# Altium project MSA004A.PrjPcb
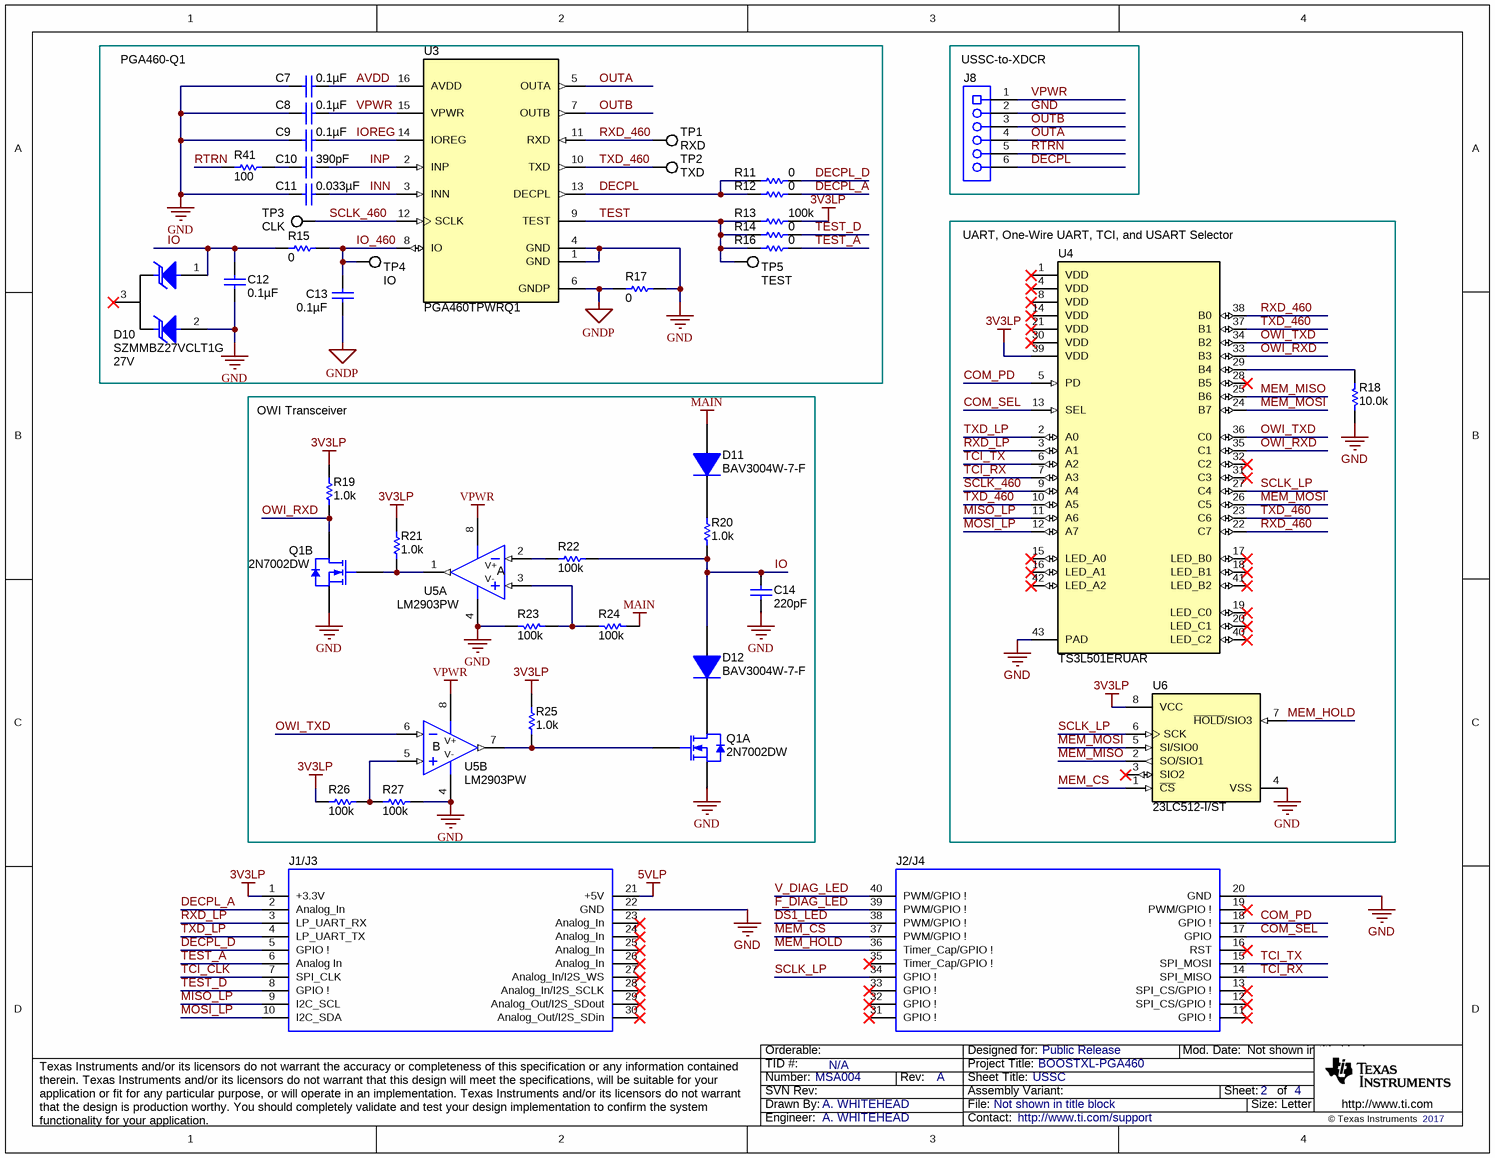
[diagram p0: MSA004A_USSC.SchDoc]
TID: N/A; TechSupport: http://www.ti.com/support; SCH_Rev: A; PRJ_Title: BOOSTXL-PGA460; PRJ_Number: MSA004; PRJ_Engineer: A. WHITEHEAD; PRJ_Customer: Public Release; PCB_Rev: A; PCB_Layout: A. WHITEHEAD; CopyrightYear: 2017
4 sheets, 119 parts. Net scope: global (net labels, ports and power ports of the same name join across sheets).
Board file: MSA004A_PCB.PcbDoc
Sheets:
  MSA004A_USSC.SchDoc
  MSA004A_HW.SchDoc
  MSA004A_XDCR.SchDoc
  MSA004A_PWR.SchDoc

## Sheet MSA004A_USSC.SchDoc: USSC
size Letter; Date: Not shown in title block; ApprovedBy: Not shown in title block; CheckedBy: Not shown in title block; Author: Not shown in title block; CompanyName: Not shown in title block; DrawnBy: A. WHITEHEAD; Engineer: Not shown in title block; Organization: Not shown in title block; Address1: Not shown in title block; Address2: Not shown in title block; Address3: Not shown in title block; Address4: Not shown in title block; DocumentNumber: 1; Revision: Use project parameter SCH_Rev; SheetNumber: 2; SheetTotal: 4; PageSetup: Record=PageOptions¦CenterHorizontal=True¦CenterVertical=True¦PrintScale=1.00¦XCorrection=1.00¦YCorrection=1.00¦PrintKind=0¦BorderSize=5000000¦LeftOffset=0¦BottomOffset=0¦Orientation=2¦PaperLength=1000¦PaperWidth=1000¦Scale=100¦PaperSource=15¦PrintQuality=600¦MediaType=1¦DitherType=10¦PaperKind=Letter¦PrintScaleMode=1

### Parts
C7  ValueDisplayed: 0.1µF  [0603]  (hidden comment: C1608X7R1H104K080AA)
C8  ValueDisplayed: 0.1µF  [0603]  (hidden comment: C1608X7R1H104K080AA)
C9  ValueDisplayed: 0.1µF  [0603]  (hidden comment: C1608X7R1H104K080AA)
C10  ValueDisplayed: 390pF  [0603]  (hidden comment: GRM1885C2A391JA01D)
C11  ValueDisplayed: 0.033µF  [0603]  (hidden comment: GRM188R71H333KA61D)
C12  ValueDisplayed: 0.1µF  [0603]  (hidden comment: C1608X7R1H104K080AA)
C13  ValueDisplayed: 0.1µF  [0603]  (hidden comment: C1608X7R1H104K080AA)
C14  ValueDisplayed: 220pF  [0603]  (hidden comment: C0603C221K5RACTU)
D10  SZMMBZ27VCLT1G  value 27V  [SOT-23]
D11  BAV3004W-7-F  [SOD-123]
D12  BAV3004W-7-F  [SOD-123]
J1/J3  SSQ-110-03-T-D  [BoosterPack_40pin_J1J3]  (value not drawn)
J2/J4  SSQ-110-03-T-D  [BoosterPack_40pin_J2J4]  (value not drawn)
J8  PPPC061LGBN-RC  [Sullins_xPxC061LGBN]  (value not drawn)
Q1  2N7002DW  [SOT-363]  (parts A,B of 2)
R11  ValueDisplayed: 0  [0402]  (hidden comment: CRCW04020000Z0ED)
R12  ValueDisplayed: 0  [0402]  (hidden comment: CRCW04020000Z0ED)
R13  ValueDisplayed: 100k  [0402]  (hidden comment: CRCW0402100KJNED)
R14  ValueDisplayed: 0  [0402]  (hidden comment: CRCW04020000Z0ED)
R15  ValueDisplayed: 0  [1206]  (hidden comment: CRCW12060000Z0EA)
R16  ValueDisplayed: 0  [0402]  (hidden comment: CRCW04020000Z0ED)
R17  ValueDisplayed: 0  [1206]  (hidden comment: CRCW12060000Z0EA)
R18  ValueDisplayed: 10.0k  [0402]  (hidden comment: CRCW040210K0FKED)
R19  ValueDisplayed: 1.0k  [0603]  (hidden comment: CRCW06031K00JNEA)
R20  ValueDisplayed: 1.0k  [2010]  (hidden comment: CRCW20101K00JNEF)
R21  ValueDisplayed: 1.0k  [0603]  (hidden comment: CRCW06031K00JNEA)
R22  ValueDisplayed: 100k  [0603]  (hidden comment: CRCW0603100KJNEA)
R23  ValueDisplayed: 100k  [0603]  (hidden comment: CRCW0603100KJNEA)
R24  ValueDisplayed: 100k  [0603]  (hidden comment: CRCW0603100KJNEA)
R25  ValueDisplayed: 1.0k  [0603]  (hidden comment: CRCW06031K00JNEA)
R26  ValueDisplayed: 100k  [0603]  (hidden comment: CRCW0603100KJNEA)
R27  ValueDisplayed: 100k  [0603]  (hidden comment: CRCW0603100KJNEA)
R41  ValueDisplayed: 100  [0603]  (hidden comment: CRCW0603100RFKEA)
TP1  RXD  [Testpoint_Keystone_Miniature]
TP2  TXD  [Testpoint_Keystone_Miniature]
TP3  CLK  [Testpoint_Keystone_Miniature]
TP4  IO  [Testpoint_Keystone_Miniature]
TP5  TEST  [Testpoint_Keystone_Miniature]
U3  PGA460TPWRQ1  [PW0016A_N]
U4  TS3L501ERUAR  [RUA0042A]
U5  LM2903PW  [PW0008A_N]  (parts A,B of 2)
U6  23LC512-I/ST  [TSSOP-8]

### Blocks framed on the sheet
PGA460-Q1: C7-C13 D10 R11-R17 R41 TP1-TP5 U3
USSC-to-XDCR: J8
UART, One-Wire UART, TCI, and USART Selector: R18 U4 U6
OWI Transceiver: C14 D11 D12 Q1 R19-R27 U5

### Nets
3V3LP: J1/J3.1(+3.3V) R13.2 R19.1 R21.2 R25.2 R26.1 U4.39(VDD) U6.8(VCC)
5VLP: J1/J3.21(+5V)
GND: C7.2 C8.2 C9.2 C11.2 C12.2 C14.2 D10.2 J1/J3.22(GND) J2/J4.20(GND) J8.2 Q1.1(S) Q1.4(S) R17.1 R18.2 R23.1 R27.1 U3.1(GND) U3.4(GND) U4.43(PAD) U5.4(V-) U6.4(VSS)
GNDP: C13.2 R17.2 U3.6(GNDP)
MAIN: D11.2(A) R24.2
VPWR: C8.1 J8.1 U3.15(VPWR) U5.8(V+)
AVDD: C7.1 U3.16(AVDD)
COM_PD: J2/J4.18(GPIO_!) U4.5(PD)
COM_SEL: J2/J4.17(GPIO) U4.13(SEL)
DECPL: J8.6 R11.1 R12.1 U3.13(DECPL)
DECPL_A: J1/J3.2(Analog_In) R12.2
DECPL_D: J1/J3.5(GPIO_!) R11.2
DS1_LED: J2/J4.38(PWM/GPIO_!)
F_DIAG_LED: J2/J4.39(PWM/GPIO_!)
INN: C11.1 U3.3(INN)
INP: C10.1 U3.2(INP)
IO: C12.1 C14.1 D10.1 D12.2(A) R15.1 R20.1 R22.2
IO_460: C13.1 R15.2 TP4.1 U3.8(IO)
IOREG: C9.1 U3.14(IOREG)
MEM_CS: J2/J4.37(PWM/GPIO_!) U6.1(~{CS})
MEM_HOLD: J2/J4.36(Timer_Cap/GPIO_!) U6.7(~{HOLD}/SIO3)
MEM_MISO: U4.25(B6) U6.2(SO/SIO1)
MEM_MOSI: U4.24(B7) U4.26(C5) U6.5(SI/SIO0)
MISO_LP: J1/J3.9(I2C_SCL) U4.11(A6)
MOSI_LP: J1/J3.10(I2C_SDA) U4.12(A7)
OUTA: J8.4 U3.5(OUTA)
OUTB: J8.3 U3.7(OUTB)
OWI_RXD: Q1.3(D) R19.2 U4.33(B3) U4.35(C1)
OWI_TXD: U4.34(B2) U4.36(C0) U5.6(IN-)
RTRN: J8.5 R41.1
RXD_460: TP1.1 U3.11(RXD) U4.22(C7) U4.38(B0)
RXD_LP: J1/J3.3(LP_UART_RX) U4.3(A1)
SCLK_460: TP3.1 U3.12(SCLK) U4.9(A4)
SCLK_LP: J2/J4.34(GPIO_!) U4.27(C4) U6.6(SCK)
TCI_CLK: J1/J3.7(SPI_CLK)
TCI_RX: J2/J4.14(SPI_MISO) U4.7(A3)
TCI_TX: J2/J4.15(SPI_MOSI) U4.6(A2)
TEST: R13.1 R14.1 R16.1 TP5.1 U3.9(TEST)
TEST_A: J1/J3.6(Analog_In) R16.2
TEST_D: J1/J3.8(GPIO_!) R14.2
TXD_460: TP2.1 U3.10(TXD) U4.10(A5) U4.23(C6) U4.37(B1)
TXD_LP: J1/J3.4(LP_UART_TX) U4.2(A0)
V_DIAG_LED: J2/J4.40(PWM/GPIO_!)
NetC10_2: C10.2 R41.2
NetD11_1: D11.1(K) R20.2
NetD12_1: D12.1(K) Q1.6(D)
NetQ1_2: Q1.2(G) R25.1 U5.7(OUT)
NetQ1_5: Q1.5(G) R21.1 U5.1(OUT)
NetR18_1: R18.1 U4.29(B4)
NetR22_1: R22.1 U5.2(IN-)
NetR23_2: R23.2 R24.1 U5.3(IN+)
NetR26_2: R26.2 R27.2 U5.5(IN+)

Not connected (* = marked no-connect by the designer): D10 3*; J1/J3 23(Analog_In)* 24(Analog_In)* 25(Analog_In)* 26(Analog_In)* 27(Analog_In/I2S_WS)* 28(Analog_In/I2S_SCLK)* 29(Analog_Out/I2S_SDout)* 30(Analog_Out/I2S_SDin)*; J2/J4 11(GPIO_!)* 12(SPI_CS/GPIO_!)* 13(SPI_CS/GPIO_!)* 16(RST)* 19(PWM/GPIO_!)* 31(GPIO_!)* 32(GPIO_!)* 33(GPIO_!)* 35(Timer_Cap/GPIO_!)*; U4 1(VDD)* 4(VDD)* 8(VDD)* 14(VDD)* 15(LED_A0)* 16(LED_A1)* 17(LED_B0)* 18(LED_B1)* 19(LED_C0)* 20(LED_C1)* 21(VDD)* 28(B5)* 30(VDD)* 31(C3)* 32(C2)* 40(LED_C2)* 41(LED_B2)* 42(LED_A2)*; U6 3(SIO2)*

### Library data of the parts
C7-C9 C12 C13 = C1608X7R1H104K080AA: CAP, CERM, 0.1 µF, 50 V, +/- 10%, X7R, 0603; Manufacturer: TDK; Polarized: N; CompType: Capacitor; Value: 0.1uF; U/M: EA; Cap_F: 0.0000001; Tolerance_%: 10; Value1: Unknown; VDC_V: 50; Value2: 50V; TaMin_C: -55; TaMax_C: 125; AEC Category: Q200
C10 = GRM1885C2A391JA01D: CAP, CERM, 390 pF, 100 V, +/- 5%, C0G/NP0, 0603; Manufacturer: MuRata; Polarized: N; CompType: Capacitor; Value: 390pF; U/M: EA; Cap_F: 0.00000000039; Tolerance_%: 5; Value1: Unknown; VDC_V: 100; Value2: 100V; TaMin_C: -55; TaMax_C: 125; AEC Category: Q200; SizeArea_mm2: 1.28; SizeAreaWB_mm2: 4.68; SizeX_mm: 1.6; SizeY_mm: 0.8; SizeZ_mm: 1
C11 = GRM188R71H333KA61D: CAP, CERM, 0.033 µF, 50 V, +/- 10%, X7R, 0603; Manufacturer: MuRata; Polarized: N; CompType: Capacitor; Value: 0.033uF; U/M: EA; Cap_F: 0.000000033; Tolerance_%: 10; Value1: Unknown; VDC_V: 50; Value2: 50V; TaMin_C: -55; TaMax_C: 125; AEC Category: Q200; SizeArea_mm2: 1.28; SizeAreaWB_mm2: 4.68; SizeX_mm: 1.6; SizeY_mm: 0.8; SizeZ_mm: 1
C14 = C0603C221K5RACTU: CAP, CERM, 220 pF, 50 V, +/- 10%, X7R, 0603; Manufacturer: Kemet; Polarized: N; CompType: Capacitor; Value: 220pF; U/M: EA; Cap_F: 0.00000000022; Tolerance_%: 10; Value1: Unknown; VDC_V: 50; Value2: 50V; TaMin_C: -55; TaMax_C: 125; AEC Category: Q200
D10 = SZMMBZ27VCLT1G: Diode, TVS, Uni, 27 V, 40 W, SOT-23; Manufacturer: ON Semiconductor; SymbolCreator: a0411947; U/M: EA; Power_W: 40; Vr_V: 27; Value1: 40W; RJA_CperW: 556; SizeAreaWB_mm2: 14; SizeArea_mm2: 7.5; SizeX_mm: 2.5; SizeY_mm: 3; SizeZ_mm: 1.1; AEC Category: Q101
D11 D12 = BAV3004W-7-F: Diode, Switching, 350 V, 0.225 A, SOD-123; Manufacturer: Diodes Inc.; U/M: EA; Vf_V: 1.25; Value: 350V; Value1: 0.225A; Value2: 1.25V; Io_A: 0.225; Vr_V: 350; TJmax_C: 150; AEC Category: Q101
J1/J3 = BoosterPack_40pin_J1J3: Receptacle, 2.54mm, 10x2, Tin, TH; Manufacturer: Samtec; Alternate Manufacturer: Major League Electronics; Alternate PartNumber: CRD-081413-A-G; SymbolCreator: a0412235; Note: Booster Pack 40 pin J1 and J3
J2/J4 = BoosterPack_40pin_J2J4: Receptacle, 2.54mm, 10x2, Tin, TH; Manufacturer: Samtec; Alternate Manufacturer: Major League Electronics; Alternate PartNumber: CRD-081413-A-G; SymbolCreator: a0412235; Note: Booster Pack 40 pin J2 and J4
J8 = PPPC061LGBN-RC: Receptacle, 2.54mm, 6x1, Gold, R/A, Black, TH; Manufacturer: Sullins Connector Solutions; SymbolCreator: a0411947; Pitch_mm: 2.54; Gender: Female; Row_Count: 1; Current_A: 3; Voltage_V: 250; Cert_UL: Y
Q1 = 2N7002DW: MOSFET, N-CH, 60 V, 0.115 A, SOT-363; Manufacturer: Fairchild Semiconductor; Alternate Manufacturer: None; U/M: EA; ChType: N; Value: 60V; VdsMax_V: 60; Value1: ? ohm; Value2: ? nC; Vgs_V: 20; IdsMax_A: 0.115; SizeAreaWB_mm2: 10.24; SizeArea_mm2: 4.84; SizeX_mm: 2.2; SizeZ_mm: 1.1; AEC Category: Q101
R11 R12 R14 R16 = CRCW04020000Z0ED: RES, 0, 5%, 0.063 W, 0402; Manufacturer: Vishay-Dale; CompType: Resistor; Value: 0; Value_Code: 0000; Tolerance_%: 5; Power_W: 0.063; Value2: 0.063W; VDC_V: 50; TempCo: 200 ppm/C; SizeArea_mm2: 0.5; SizeX_mm: 1; SizeZ_mm: 0.6; EIA_Code: E24; U/M: EA; AEC Category: Q200
R13 = CRCW0402100KJNED: RES, 100 k, 5%, 0.063 W, 0402; Manufacturer: Vishay-Dale; CompType: Resistor; Value: 100k; Res_ohm: 100000; Tolerance_%: 5; Power_W: 0.063; Value2: 0.063W; VDC_V: 50; TempCo: 200 ppm/C; SizeArea_mm2: 0.5; SizeX_mm: 1; SizeZ_mm: 0.6; EIA_Code: E24; U/M: EA; AEC Category: Q200
R15 = CRCW12060000Z0EA: RES, 0, 5%, 0.25 W, 1206; Manufacturer: Vishay-Dale; CompType: Resistor; Value: 0; Value_Code: 0000; Tolerance_%: 5; Power_W: 0.25; Value2: 0.25W; VDC_V: 200; TempCo: 200 ppm/C; EIA_Code: E24; U/M: EA; AEC Category: Q200; SizeArea_mm2: 5.12; SizeX_mm: 3.2; SizeY_mm: 1.6; SizeZ_mm: 1.35
R17 = CRCW12060000Z0EA: RES, 0, 5%, 0.25 W, 1206; Manufacturer: Vishay-Dale; CompType: Resistor; Value: 0; Value2: 0.25W; Value_Code: 0000; Tolerance_%: 5; Power_W: 0.25; VDC_V: 200; TempCo: 200 ppm/C; EIA_Code: E24; U/M: EA; AEC Category: Q200; SizeArea_mm2: 5.12; SizeX_mm: 3.2; SizeY_mm: 1.6; SizeZ_mm: 1.35
R18 = CRCW040210K0FKED: RES, 10.0 k, 1%, 0.063 W, 0402; Manufacturer: Vishay-Dale; CompType: Resistor; Value: 10.0k; Res_ohm: 10000; Value_Code: 10k0; Tolerance_%: 1; Power_W: 0.063; Value2: 0.063W; VDC_V: 50; TempCo: 100 ppm/C; SizeArea_mm2: 0.5; SizeZ_mm: 0.6; EIA_Code: E96; U/M: EA; AEC Category: Q200
R19 R21 R25 = CRCW06031K00JNEA: RES, 1.0 k, 5%, 0.1 W, 0603; Manufacturer: Vishay-Dale; CompType: Resistor; Value: 1.0k; Res_ohm: 1000; Value_Code: 1k00; Tolerance_%: 5; Power_W: 0.1; Value2: 0.1W; VDC_V: 75; TempCo: 200 ppm/C; SizeArea_mm2: 1.28; SizeX_mm: 1.6; SizeY_mm: 0.8; SizeZ_mm: 1; EIA_Code: E24; U/M: EA; AEC Category: Q200
R20 = CRCW20101K00JNEF: RES, 1.0 k, 5%, 0.75 W, AEC-Q200 Grade 0, 2010; Manufacturer: Vishay-Dale; CompType: Resistor; Value: 1.0k; Res_ohm: 1000; Value_Code: 1k00; Tolerance_%: 5; Power_W: 0.75; Value2: 0.75W; VDC_V: 400; TempCo: 200 ppm/C; SizeArea_mm2: 12.5; SizeY_mm: 2.5; SizeZ_mm: 1.66; EIA_Code: E24; U/M: EA; AEC Category: Q200; AEC Qualified: Y; AEC Grade: 0
R22-R24 R26 R27 = CRCW0603100KJNEA: RES, 100 k, 5%, 0.1 W, 0603; Manufacturer: Vishay-Dale; CompType: Resistor; Value: 100k; Res_ohm: 100000; Tolerance_%: 5; Power_W: 0.1; Value2: 0.1W; VDC_V: 75; TempCo: 200 ppm/C; EIA_Code: E24; U/M: EA; AEC Category: Q200
R41 = CRCW0603100RFKEA: RES, 100, 1%, 0.1 W, 0603; Manufacturer: Vishay-Dale; CompType: Resistor; Value: 100; Value_Code: 100R; Tolerance_%: 1; Power_W: 0.1; Value2: 0.1W; VDC_V: 75; TempCo: 100 ppm/C; SizeArea_mm2: 1.28; SizeX_mm: 1.6; SizeY_mm: 0.8; EIA_Code: E96; U/M: EA; AEC Category: Q200
TP1-TP5 = 5015: Test Point, Miniature, SMT; Manufacturer: Keystone; CompType: Test Point Loop
U3 = PGA460TPWRQ1: PGA460TPWRQ1, PW0016A; Manufacturer: Texas Instruments; SymbolCreator: Altium; SizeArea_mm2: 32; SizeAreaWB_mm2: 58.8; SizeX_mm: 6.4; SizeY_mm: 5; SizeZ_mm: 1.2; CompType: IC; U/M: EA
U4 = TS3L501ERUAR: 16-BIT TO 8-BIT MULTIPLEXER/DEMULTIPLEXER GIGABIT ETHERNET LAN SWITCH WITH POWER DOWN MODE, RUA0042A; Manufacturer: Texas Instruments; SymbolCreator: a0411947; SizeArea_mm2: 31.5; SizeAreaWB_mm2: 60.5; SizeX_mm: 3.5; SizeY_mm: 9; SizeZ_mm: 0.8; CompType: IC; U/M: EA
U5 = LM2903PW: Dual Comparator, PW0008A; Manufacturer: Texas Instruments; CompType: OpAmp IC
U6 = 23LC512-I/ST: 512Kbit SPI Serial SRAM with SDI and SQI Interface,; Manufacturer: Microchip; SymbolCreator: a0411947

## Sheet MSA004A_HW.SchDoc: Hardware
size Letter; Date: Not shown in title block; ApprovedBy: Not shown in title block; CheckedBy: Not shown in title block; Author: Not shown in title block; CompanyName: Not shown in title block; DrawnBy: A. WHITEHEAD; Engineer: Not shown in title block; Organization: Not shown in title block; Address1: Not shown in title block; Address2: Not shown in title block; Address3: Not shown in title block; Address4: Not shown in title block; DocumentNumber: 2; Revision: Use project parameter SCH_Rev; SheetNumber: 4; SheetTotal: 4; PageSetup: Record=PageOptions¦CenterHorizontal=True¦CenterVertical=True¦PrintScale=1.00¦XCorrection=1.00¦YCorrection=1.00¦PrintKind=0¦BorderSize=5000000¦LeftOffset=0¦BottomOffset=0¦Orientation=2¦PaperLength=1000¦PaperWidth=1000¦Scale=100¦PaperSource=15¦PrintQuality=600¦MediaType=1¦DitherType=10¦PaperKind=Letter¦PrintScaleMode=1
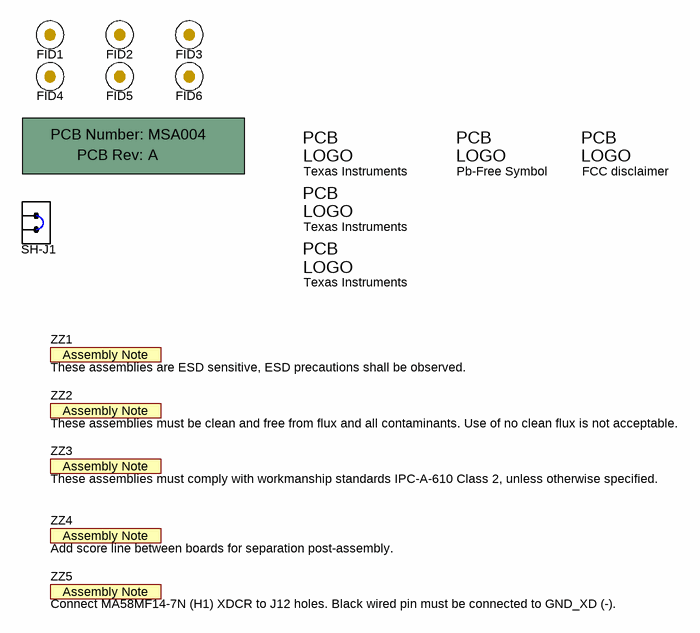
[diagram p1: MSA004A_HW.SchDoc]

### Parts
!PCB1  Printed Circuit Board  (value not drawn)  (mechanical)
FID1  Fiducial  [Fiducial10-20]  (value not drawn)
FID2  Fiducial  [Fiducial10-20]  (value not drawn)
FID3  Fiducial  [Fiducial10-20]  (value not drawn)
FID4  Fiducial  [Fiducial10-20]  (value not drawn)
FID5  Fiducial  [Fiducial10-20]  (value not drawn)
FID6  Fiducial  [Fiducial10-20]  (value not drawn)
Logo1  Texas Instruments  [TI_Stacked_Overlay_Small]  (no BOM)
Logo2  Pb-Free Symbol  [Pb-Free_Overlay_Small]  (no BOM)
Logo3  FCC disclaimer  [FCC_disclaimer]  (no BOM)
Logo4  Texas Instruments  [TI_Symbol_Overlay_Small]  (no BOM)
Logo5  Texas Instruments  [TI_Symbol_Overlay_Small]  (no BOM)
SH-J1  60900213421  [Wurth_60900213421]  (value not drawn)
ZZ1  These assemblies are ESD sensitive, ESD precautions shall be observed.  [AssemblyNote]  (no BOM)
ZZ2  These assemblies must be clean and free from flux and all contaminants. Use of no clean flux is not acceptable.  [AssemblyNote]  (no BOM)
ZZ3  These assemblies must comply with workmanship standards IPC-A-610 Class 2, unless otherwise specified.  [AssemblyNote]  (no BOM)
ZZ4  Add score line between boards for separation post-assembly.  [AssemblyNote]  (no BOM)
ZZ5  Connect MA58MF14-7N (H1) XDCR to J12 holes. Black wired pin must be connected to GND_XD (-).  [AssemblyNote]  (no BOM)

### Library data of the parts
!PCB1 = PCB: Manufacturer: Any; PartNumber: MSA004; SymbolCreator: a0412235
FID1-FID6 = Fiducial: Fiducial mark.  There is nothing to buy or mount.; SymbolCreator: codlsc
Logo1 Logo4 Logo5 = TI_Logo: Texas Instrument Corporate Signature; SymbolCreator: codlsc
Logo2 = Pb-Free: SymbolCreator: a0412235
Logo3 = FCC_disclaimer: SymbolCreator: codlsc
SH-J1 = 60900213421: Shunt, 2.54mm, Gold, Black; Manufacturer: Wurth Elektronik
ZZ1-ZZ5 = AssemblyNote: SymbolCreator: codlsc

## Sheet MSA004A_XDCR.SchDoc: Sensor
size Letter; Date: Not shown in title block; ApprovedBy: Not shown in title block; CheckedBy: Not shown in title block; Author: Not shown in title block; CompanyName: Not shown in title block; DrawnBy: A. WHITEHEAD; Engineer: Not shown in title block; Organization: Not shown in title block; Address1: Not shown in title block; Address2: Not shown in title block; Address3: Not shown in title block; Address4: Not shown in title block; DocumentNumber: 1; Revision: Use project parameter SCH_Rev; SheetNumber: 3; SheetTotal: 4; PageSetup: Record=PageOptions¦CenterHorizontal=True¦CenterVertical=True¦PrintScale=0.98¦XCorrection=1.00¦YCorrection=1.00¦PrintKind=0¦BorderSize=5000000¦LeftOffset=0¦BottomOffset=0¦Orientation=2¦PaperLength=1000¦PaperWidth=1000¦Scale=100¦PaperSource=15¦PrintQuality=600¦MediaType=1¦DitherType=10¦PrintScaleMode=1¦PaperKind=Letter
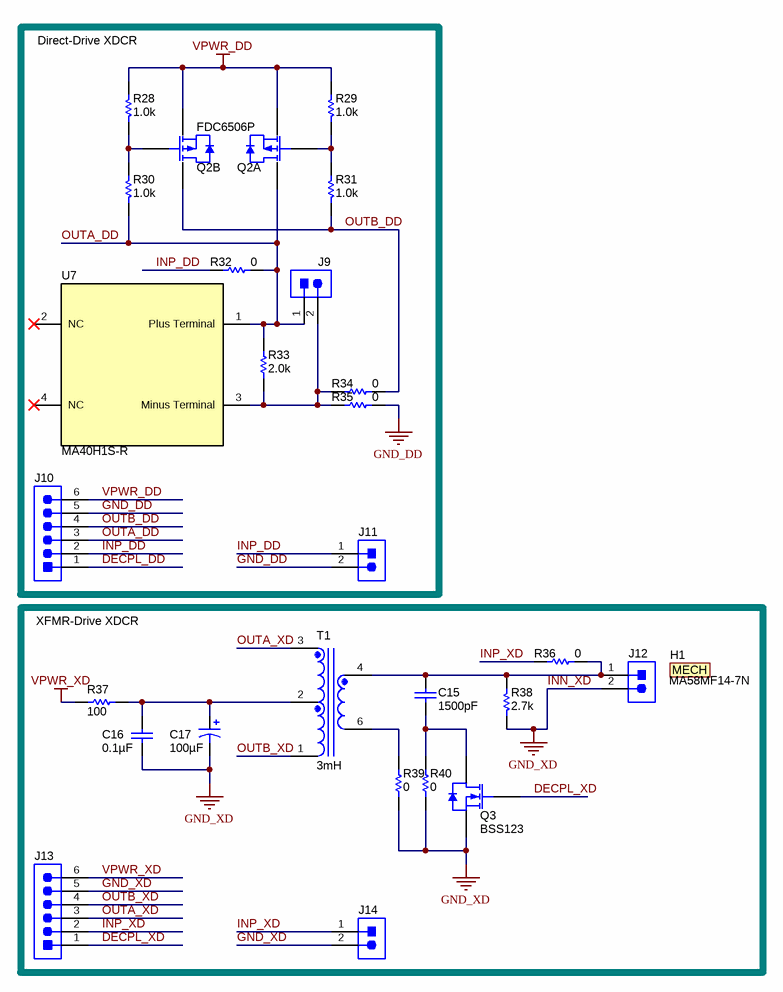
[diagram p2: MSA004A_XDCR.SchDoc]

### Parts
C15  ValueDisplayed: 1500pF  [0805_HV]  (hidden comment: GRM2165C2A152JA01D)
C16  ValueDisplayed: 0.1µF  [0603]  (hidden comment: C1608X7R1H104K080AA)
C17  ValueDisplayed: 100µF  [CAPSMT_62_F80]  (hidden comment: EMVA350ADA101MF80G)
H1  MA58MF14-7N  (mechanical)
J9  PEC02SAAN  [CONN_PEC02SAAN]  (value not drawn)
J10  PBC06SAAN  [Sullins_PxC06SAAN]  (value not drawn)
J11  PEC02SAAN  [CONN_PEC02SAAN]  (value not drawn)
J12  PEC02SAAN  [CONN_PEC02SAAN]  (value not drawn)
J13  PBC06SAAN  [Sullins_PxC06SAAN]  (value not drawn)
J14  PEC02SAAN  [CONN_PEC02SAAN]  (value not drawn)
Q2  FDC6506P  [superSOT-6]  (parts A,B of 2)
Q3  BSS123  [SOT-23]
R28  ValueDisplayed: 1.0k  [0603]  (hidden comment: CRCW06031K00JNEA)
R29  ValueDisplayed: 1.0k  [0603]  (hidden comment: CRCW06031K00JNEA)
R30  ValueDisplayed: 1.0k  [0603]  (hidden comment: CRCW06031K00JNEA)
R31  ValueDisplayed: 1.0k  [0603]  (hidden comment: CRCW06031K00JNEA)
R32  ValueDisplayed: 0  [1206]  (hidden comment: CRCW12060000Z0EA)
R33  ValueDisplayed: 2.0k  [0402]  (hidden comment: CRCW04022K00JNED)
R34  ValueDisplayed: 0  [1206]  (hidden comment: CRCW12060000Z0EA)
R35  ValueDisplayed: 0  [1206]  (hidden comment: CRCW12060000Z0EA)
R36  ValueDisplayed: 0  [1206]  (hidden comment: CRCW12060000Z0EA)
R37  ValueDisplayed: 100  [0805_HV]  (hidden comment: CRCW0805100RJNEA)
R38  ValueDisplayed: 2.7k  [1206]  (hidden comment: CRCW12062K70JNEA)
R39  ValueDisplayed: 0  [1206]  (hidden comment: CRCW12060000Z0EA)
R40  ValueDisplayed: 0  [1206]  (hidden comment: CRCW12060000Z0EA)
T1  ValueDisplayed: 3mH  [TDK_B78416A2232A003]  (hidden comment: B78416A2232A003)
U7  MA40H1S-R  [MA40H1S]

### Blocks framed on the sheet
Direct-Drive XDCR: J9-J11 Q2 R28-R35 U7
XFMR-Drive XDCR: C15-C17 H1 J12-J14 Q3 R36-R40 T1

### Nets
GND_DD: J10.5 J11.2 R35.1
GND_XD: C16.1 C17.2(-) J12.2 J13.5 J14.2 Q3.2(S) R38.1 R39.1 R40.1  [also labelled INN_XD]
VPWR_DD: J10.6 Q2.2(S) Q2.5(S) R28.2 R29.2
VPWR_XD: J13.6 R37.1
DECPL_DD: J10.1
DECPL_XD: J13.1 Q3.1(G)
INP_DD: J10.2 J11.1 R32.2
INP_XD: J13.2 J14.1 R36.2
OUTA_DD: J9.1 J10.3 Q2.6(D) R30.2 R32.1 R33.2 U7.1(Plus_Terminal)
OUTA_XD: J13.3 T1.3
OUTB_DD: J10.4 Q2.4(D) R31.2 R34.1
OUTB_XD: J13.4 T1.1
NetC15_1: C15.1 J12.1 R36.1 R38.2 T1.4
NetC15_2: C15.2 Q3.3(D) R40.2
NetC16_2: C16.2 C17.1(+) R37.2 T1.2
NetJ9_2: J9.2 R33.1 R34.2 R35.2 U7.3(Minus_Terminal)
NetQ2_1: Q2.1(G) R29.1 R31.1
NetQ2_3: Q2.3(G) R28.1 R30.1
NetR39_2: R39.2 T1.6

Not connected (* = marked no-connect by the designer): U7 2(NC)* 4(NC)*

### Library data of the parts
C15 = GRM2165C2A152JA01D: CAP, CERM, 1500 pF, 100 V, +/- 5%, C0G/NP0, 0805; Manufacturer: MuRata; Polarized: N; CompType: Capacitor; Value: 1500pF; U/M: EA; Cap_F: 0.0000000015; Tolerance_%: 5; Value1: Unknown; VDC_V: 100; Value2: 100V; TaMin_C: -55; TaMax_C: 125; Cap_Case: 0805; AEC Category: Q200
C16 = C1608X7R1H104K080AA: as C7 on sheet MSA004A_USSC
C17 = EMVA350ADA101MF80G: CAP, AL, 100 µF, 35 V, +/- 20%, SMD; Manufacturer: Chemi-Con; Polarized: Y; CompType: Capacitor; Value: 100uF; U/M: EA; Cap_F: 0.0001; Tolerance_%: 20; Value1: Unknown; VDC_V: 35; Value2: 35V; IRMS_A: 0.12; TaMin_C: -40; TaMax_C: 85; Cap_Case: F80; AEC Category: Q200
H1 = MA58MF14-7N: Ultrasonic Transducer; Manufacturer: MuRata; SymbolCreator: codlsc; CompType: Sensor
J9 J11 J12 J14 = PEC02SAAN: Header, 100mil, 2x1, Tin, TH; Manufacturer: Sullins Connector Solutions; SymbolCreator: a0412235; U/M: EA
J10 J13 = PBC06SAAN: Header, 2.54mm, 6x1, Gold, TH; Manufacturer: Sullins Connector Solutions; SymbolCreator: a0412235; Pitch_mm: 2.54; Gender: Male; Shrouded: N; Row_Count: 1; Current_A: 3; Cert_UL: Y
Q2 = FDC6506P: MOSFET, P-CH, -30 V, -1.8 A, superSOT-6; Manufacturer: Fairchild Semiconductor; Alternate Manufacturer: None; SymbolCreator: a0412235; U/M: EA; ChType: P; Value: -30V; Value1: 0.28 ohm; Rdson45_ohm: 0.28; Value2: 2.3 nC; QgTyp_nC: 2.3; Vgs_V: 20; SizeAreaWB_mm2: 14.82; SizeArea_mm2: 8.12; SizeX_mm: 2.8; SizeY_mm: 2.9; SizeZ_mm: 1.1; AEC Category: Q101; AEC Qualified: N
Q3 = BSS123: MOSFET, N-CH, 100 V, 0.17 A, SOT-23; Manufacturer: Fairchild Semiconductor; Alternate Manufacturer: None; U/M: EA; ChType: N; Value: 100V; VdsMax_V: 100; Value1: 10 ohm; Rdson45_ohm: 10; Value2: 1.8 nC; QgTyp_nC: 1.8; Vgs_V: 20; IdsMax_A: 0.17; SizeAreaWB_mm2: 14; SizeArea_mm2: 7.5; SizeX_mm: 2.5; SizeY_mm: 3; SizeZ_mm: 1.1; AEC Category: Q101
R28-R31 = CRCW06031K00JNEA: RES, 1.0 k, 5%, 0.1 W, 0603; Manufacturer: Vishay-Dale; CompType: Resistor; Value: 1.0k; Res_ohm: 1000; Value_Code: 1k00; Tolerance_%: 5; Power_W: 0.1; Value2: 0.1W; VDC_V: 75; TempCo: 200 ppm/C; EIA_Code: E24; U/M: EA; AEC Category: Q200
R32 R34-R36 R39 R40 = CRCW12060000Z0EA: RES, 0, 5%, 0.25 W, 1206; Manufacturer: Vishay-Dale; CompType: Resistor; Value: 0; Value_Code: 0000; Tolerance_%: 5; Power_W: 0.25; Value2: 0.25W; VDC_V: 200; TempCo: 200 ppm/C; SizeArea_mm2: 5.12; SizeX_mm: 3.2; SizeY_mm: 1.6; SizeZ_mm: 1.35; EIA_Code: E24; U/M: EA; AEC Category: Q200
R33 = CRCW04022K00JNED: RES, 2.0 k, 5%, 0.063 W, 0402; Manufacturer: Vishay-Dale; CompType: Resistor; Value: 2.0k; Res_ohm: 2000; Value_Code: 2k00; Tolerance_%: 5; Power_W: 0.063; Value2: 0.063W; VDC_V: 50; TempCo: 200 ppm/C; SizeArea_mm2: 0.5; SizeX_mm: 1; SizeZ_mm: 0.6; EIA_Code: E24; U/M: EA; AEC Category: Q200
R37 = CRCW0805100RJNEA: RES, 100, 5%, 0.125 W, 0805; Manufacturer: Vishay-Dale; CompType: Resistor; Value: 100; Value_Code: 100R; Tolerance_%: 5; Power_W: 0.125; Value2: 0.125W; VDC_V: 150; TempCo: 200 ppm/C; SizeArea_mm2: 2.5; SizeX_mm: 2; SizeY_mm: 1.25; SizeZ_mm: 1.45; EIA_Code: E24; U/M: EA; AEC Category: Q200
R38 = CRCW12062K70JNEA: RES, 2.7 k, 5%, 0.25 W, 1206; Manufacturer: Vishay-Dale; CompType: Resistor; Value: 2.7k; Res_ohm: 2700; Value_Code: 2k70; Tolerance_%: 5; Power_W: 0.25; Value2: 0.25W; VDC_V: 200; TempCo: 200 ppm/C; EIA_Code: E24; U/M: EA; AEC Category: Q200; SizeArea_mm2: 5.12; SizeX_mm: 3.2; SizeY_mm: 1.6; SizeZ_mm: 1.35
T1 = B78416A2232A003: Transformer, 3 mH, SMT; Manufacturer: TDK; SymbolCreator: Altium; Value: 3mH; Lp: 3000; Ns1toNp: 0.1188
U7 = MA40H1S-R: Ultrasonic Transducer, 6 VPP, 40 kHz, 4500 pF, -20 to 60 degC, SMD, 4-Pin Body 5.2 x 5.2 mm; Manufacturer: MuRata; SymbolCreator: Altium

## Sheet MSA004A_PWR.SchDoc: Power
size Letter; Date: Not shown in title block; ApprovedBy: Not shown in title block; CheckedBy: Not shown in title block; Author: Not shown in title block; CompanyName: Not shown in title block; DrawnBy: A. WHITEHEAD; Engineer: Not shown in title block; Organization: Not shown in title block; Address1: Not shown in title block; Address2: Not shown in title block; Address3: Not shown in title block; Address4: Not shown in title block; DocumentNumber: 1; Revision: Use project parameter SCH_Rev; SheetNumber: 1; SheetTotal: 4; PageSetup: Record=PageOptions¦CenterHorizontal=True¦CenterVertical=True¦PrintScale=1.00¦XCorrection=1.00¦YCorrection=1.00¦PrintKind=0¦BorderSize=5000000¦LeftOffset=0¦BottomOffset=0¦Orientation=2¦PaperLength=1000¦PaperWidth=1000¦Scale=100¦PaperSource=15¦PrintQuality=600¦MediaType=1¦DitherType=10¦PaperKind=Letter¦PrintScaleMode=1
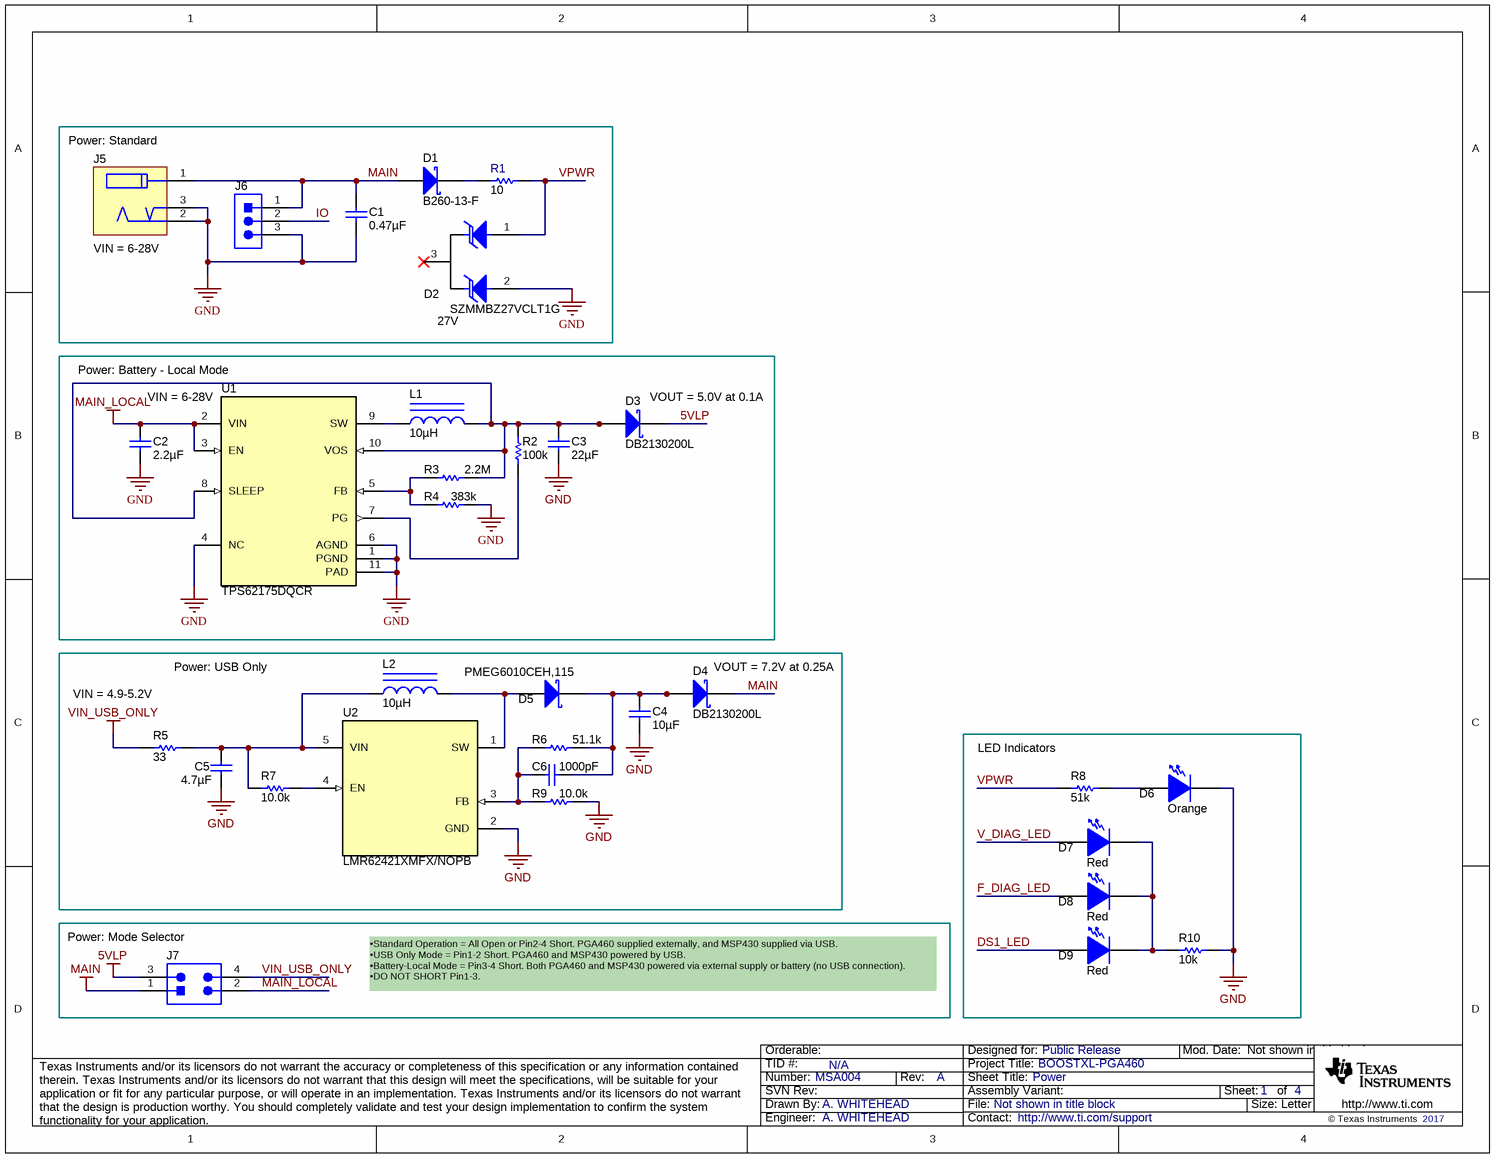
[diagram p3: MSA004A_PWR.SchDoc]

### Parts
C1  ValueDisplayed: 0.47µF  [0603]  (hidden comment: C1608X5R1H474K080AB)
C2  ValueDisplayed: 2.2µF  [1206_180]  (hidden comment: GRM31CR71H225KA88L)
C3  ValueDisplayed: 22µF  [1206_180]  (hidden comment: GRM31CR61A226KE19L)
C4  ValueDisplayed: 10µF  [0805_HV]  (hidden comment: GRM21BR61C106KE15L)
C5  ValueDisplayed: 4.7µF  [0603]  (hidden comment: GRM188R61A475MAAJ)
C6  ValueDisplayed: 1000pF  [0805_HV]  (hidden comment: CC0805KRX7R9BB102)
D1  B260-13-F  [SMB]
D2  SZMMBZ27VCLT1G  value 27V  [SOT-23]
D3  DB2130200L  [SMini2-F5-B]
D4  DB2130200L  [SMini2-F5-B]
D5  PMEG6010CEH,115  [SOD-123F]
D6  value Orange  [LTST-C191_Orange]  (hidden comment: LTST-C191KFKT)
D7  value Red  [LTST-C191_Red]  (hidden comment: LTST-C191KRKT)
D8  value Red  [LTST-C191_Red]  (hidden comment: LTST-C191KRKT)
D9  value Red  [LTST-C191_Red]  (hidden comment: LTST-C191KRKT)
J5  RASM712PX  [Switchcraft_RASM712PX]  (value not drawn)
J6  TSW-103-07-T-S  [Samtec_TSW-103-07-T-S]  (value not drawn)
J7  0015912040  [Molex_0015912040]  (value not drawn)
L1  ValueDisplayed: 10µH  [IND_LQH44P]  (hidden comment: LQH44PN100MP0L)
L2  ValueDisplayed: 10µH  [SDR0403]  (hidden comment: SDR0403-100ML)
R1  ValueDisplayed: 10  [2010]  (hidden comment: CRCW201010R0JNEF)
R2  ValueDisplayed: 100k  [0402]  (hidden comment: CRCW0402100KFKED)
R3  ValueDisplayed: 2.2M  [1206]  (hidden comment: RC1206FR-072M2L)
R4  ValueDisplayed: 383k  [0402]  (hidden comment: CRCW0402383KFKED)
R5  ValueDisplayed: 33  [2010]  (hidden comment: CRCW201033R0JNEF)
R6  ValueDisplayed: 51.1k  [0402]  (hidden comment: CRCW040251K1FKED)
R7  ValueDisplayed: 10.0k  [0402]  (hidden comment: CRCW040210K0FKED)
R8  ValueDisplayed: 51k  [0603]  (hidden comment: RC0603JR-0751KL)
R9  ValueDisplayed: 10.0k  [0402]  (hidden comment: CRCW040210K0FKED)
R10  ValueDisplayed: 10k  [0603]  (hidden comment: RC0603JR-0710KL)
U1  TPS62175DQCR  [DQC0010A]
U2  LMR62421XMFX/NOPB  [DBV0005A_N]

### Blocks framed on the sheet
LED Indicators: D6-D9 R8 R10
Power: Mode Selector: J7

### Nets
5VLP: D3.1(K) J7.3
GND: C1.2 C2.2 C3.2 C4.2 C5.2 D2.2 D6.2(K) J5.2 J5.3 J6.3 R4.2 R9.2 R10.2 U1.1(PGND) U1.4(NC) U1.6(AGND) U1.11(PAD) U2.2(GND)
MAIN: C1.1 D1.2(A) D4.1(K) J5.1 J6.1 J7.1
MAIN_LOCAL: C2.1 J7.2 U1.2(VIN) U1.3(EN)
VIN_USB_ONLY: J7.4 R5.1
VPWR: D2.1 R1.2 R8.1
DS1_LED: D9.1(A)
F_DIAG_LED: D8.1(A)
IO: J6.2
V_DIAG_LED: D7.1(A)
NetC3_1: C3.1 D3.2(A) L1.2 R2.1 R3.2 U1.8(SLEEP) U1.10(VOS)
NetC4_1: C4.1 C6.1 D4.2(A) D5.1(K) R6.2
NetC5_1: C5.1 L2.1 R5.2 R7.1 U2.5(VIN)
NetC6_2: C6.2 R6.1 R9.1 U2.3(FB)
NetD1_1: D1.1(K) R1.1
NetD5_2: D5.2(A) L2.2 U2.1(SW)
NetD6_1: D6.1(A) R8.2
NetD7_2: D7.2(K) D8.2(K) D9.2(K) R10.1
NetL1_1: L1.1 U1.9(SW)
NetR2_2: R2.2 U1.7(PG)
NetR3_1: R3.1 R4.1 U1.5(FB)
NetR7_2: R7.2 U2.4(EN)

Not connected (* = marked no-connect by the designer): D2 3*

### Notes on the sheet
- (near J5) Power: Standard
- (near J5) VIN = 6-28V
- Power: Battery - Local Mode
- VIN = 6-28V
- (near D3) VOUT = 5.0V at 0.1A
- (near R5) VIN = 4.9-5.2V
- Power: USB Only
- (near D4) VOUT = 7.2V at 0.25A
- •Standard Operation = All Open or Pin2-4 Short. PGA460 supplied externally, and MSP430 supplied via USB.
  •USB Only Mode = Pin1-2 Short. PGA460 and MSP430 powered by USB.
  •Battery-Local Mode = Pin3-4 Short. Both PGA460 and MSP430 powered via external supply or battery (no USB connection).
  •DO NOT SHORT Pin1-3.

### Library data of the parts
C1 = C1608X5R1H474K080AB: CAP, CERM, 0.47 µF, 50 V, +/- 10%, X5R, 0603; Manufacturer: TDK; Polarized: N; CompType: Capacitor; Value: 0.47uF; U/M: EA; Cap_F: 0.00000047; Tolerance_%: 10; ESR_ohm: 0.010974; Value1: 0.010974 ohm; VDC_V: 50; Value2: 50V; IRMS_A: 1.57483; TaMin_C: -55; TaMax_C: 85; SizeArea_mm2: 1.28; SizeAreaWB_mm2: 4.68; SizeX_mm: 1.6; SizeY_mm: 0.8; SizeZ_mm: 1; AEC Category: Q200
C2 = GRM31CR71H225KA88L: CAP, CERM, 2.2 µF, 50 V, +/- 10%, X7R, 1206; Manufacturer: MuRata; Polarized: N; CompType: Capacitor; Value: 2.2uF; U/M: EA; Cap_F: 0.0000022; Tolerance_%: 10; Value1: Unknown; VDC_V: 50; Value2: 50V; TaMin_C: -55; TaMax_C: 125; Cap_Case: 1206; SizeArea_mm2: 5.12; SizeAreaWB_mm2: 10.92; SizeX_mm: 3.2; SizeY_mm: 1.6; SizeZ_mm: 1.8; AEC Category: Q200
C3 = GRM31CR61A226KE19L: CAP, CERM, 22 µF, 10 V, +/- 10%, X5R, 1206; Manufacturer: MuRata; Polarized: N; CompType: Capacitor; Value: 22uF; U/M: EA; Cap_F: 0.000022; Tolerance_%: 10; Value1: Unknown; Value2: 10V; TaMin_C: -55; TaMax_C: 85; Cap_Case: 1206; SizeArea_mm2: 5.12; SizeAreaWB_mm2: 10.92; SizeX_mm: 3.2; SizeY_mm: 1.6; SizeZ_mm: 1.8; AEC Category: Q200
C4 = GRM21BR61C106KE15L: CAP, CERM, 10 µF, 16 V, +/- 10%, X5R, 0805; Manufacturer: MuRata; Polarized: N; CompType: Capacitor; Value: 10uF; U/M: EA; Cap_F: 0.00001; Tolerance_%: 10; ESR_ohm: 0.008; Value1: 0.008 ohm; VDC_V: 16; Value2: 16V; TaMin_C: -55; TaMax_C: 85; Cap_Case: 0805; SizeArea_mm2: 2.5; SizeAreaWB_mm2: 6.75; SizeX_mm: 2; SizeY_mm: 1.25; SizeZ_mm: 1.45; AEC Category: Q200
C5 = GRM188R61A475MAAJ: CAP, CERM, 4.7 µF, 10 V, +/- 20%, X5R, 0603; Manufacturer: MuRata; Polarized: N; CompType: Capacitor; Value: 4.7uF; U/M: EA; Cap_F: 0.0000047; Tolerance_%: 20; Value1: Unknown; VDC_V: 10; Value2: 10V; TaMin_C: -55; TaMax_C: 85; SizeArea_mm2: 1.28; SizeAreaWB_mm2: 4.68; SizeX_mm: 1.6; SizeY_mm: 0.8; SizeZ_mm: 1; AEC Category: Q200
C6 = CC0805KRX7R9BB102: CAP, CERM, 1000 pF, 50 V, +/- 10%, X7R, 0805; Manufacturer: Yageo America; Polarized: N; CompType: Capacitor; Value: 1000pF; U/M: EA; Cap_F: 0.000000001; Tolerance_%: 10; Value1: Unknown; VDC_V: 50; Value2: 50V; TaMin_C: -55; TaMax_C: 125; Cap_Case: 0805; SizeArea_mm2: 2.5; SizeAreaWB_mm2: 6.75; SizeX_mm: 2; SizeY_mm: 1.25; SizeZ_mm: 1.45; AEC Category: Q200
D1 = B260-13-F: Diode, Schottky, 60 V, 2 A, SMB; Manufacturer: Diodes Inc.; U/M: EA; Vf_V: 0.7; Value: 60V; Value1: 2A; Value2: 0.7V; Io_A: 2; Vr_V: 60; TJmax_C: 150; RJC_CperW: 20; AEC Category: Q101
D2 = SZMMBZ27VCLT1G: as D10 on sheet MSA004A_USSC
D3 D4 = DB2130200L: Diode, Schottky, 30 V, 1 A, SOD-323F; Manufacturer: Panasonic; U/M: EA; Vf_V: 0.38; Value: 30V; Value1: 1A; Value2: 0.38V; Io_A: 1; Vr_V: 30; TJmax_C: 125; SizeAreaWB_mm2: 7.875; SizeArea_mm2: 3.125; SizeX_mm: 2.5; SizeY_mm: 1.25; SizeZ_mm: 0.7; AEC Category: Q101
D5 = PMEG6010CEH,115: Diode, Schottky, 60 V, 1 A, SOD-123F; Manufacturer: NXP Semiconductor; U/M: EA; Vf_V: 0.57; Value: 60V; Value1: 1A; Value2: 0.57V; Io_A: 1; Vr_V: 60; TJmax_C: 150; SizeAreaWB_mm2: 11.7; SizeArea_mm2: 5.6; SizeX_mm: 3.5; SizeY_mm: 1.6; SizeZ_mm: 1.1; AEC Category: Q101
D6 = LTST-C191KFKT: LED, Orange, SMD; Manufacturer: Lite-On; Type: AlInGaP; Vf_V: 2; Value2: 2V; Io_A: 0.02; Vr_V: 5; Ir_A: 1e-005; Tjmax_C: 85; Power_TotalModule: 0.075; Value1: 0.075W; Angle: 130; U/M: EA
D7-D9 = LTST-C191KRKT: LED, Red, SMD; Manufacturer: Lite-On; Type: AlInGaP; Vf_V: 2; Value2: 2V; Io_A: 0.02; Vr_V: 5; Ir_A: 1e-005; Tjmax_C: 85; Power_TotalModule: 0.075; Value1: 0.075W; Angle: 130; U/M: EA
J5 = RASM712PX: Power Jack, 2.5mm, R/A, SMT; Manufacturer: Switchcraft; SymbolCreator: a0799628
J6 = TSW-103-07-T-S: Header, 2.54 mm, 3x1, Tin, TH; Manufacturer: Samtec; SymbolCreator: a0799628; Pitch_mm: 2.54; Gender: Male; Shrouded: N; Row_Count: 1; Current_A: 6.3; Voltage_V: 550; Cert_CSA: Y
J7 = 0015912040: Header, 2.54mm, 2x2, Gold, SMT; Manufacturer: Molex; SymbolCreator: a0412235; Pitch_mm: 2.54; Gender: Male; Shrouded: N; Row_Count: 2; ContactFinish: Tin; Current_A: 3; Voltage_V: 250; Cert_CSA: Y
L1 = LQH44PN100MP0L: Inductor, Shielded Drum Core, Ferrite, 10 µH, 1.15 A, 0.16 ohm, SMD; Manufacturer: MuRata; Value: 10uH; Ind_H: 10.0E-6; Imax_A: 1.15; Irms: 1.17A @ 40C rise; Isat: 1.15A @ 30% inductance drop; DCR_ohm: 0.16; Value2: 1.15A; AEC Category: Q200
L2 = SDR0403-100ML: Inductor, Drum Core, Ferrite, 10 µH, 1.15 A, 0.18 ohm, SMD; Manufacturer: Bourns; Value: 10uH; Ind_H: 10.0E-6; Imax_A: 1.15; Irms: 1.15A @ 40C rise; Isat: 1.67A @ 10% inductance drop; DCR_ohm: 0.18; Value2: 1.15A; AEC Category: Q200
R1 = CRCW201010R0JNEF: RES, 10, 5%, 0.75 W, 2010; Manufacturer: Vishay-Dale; CompType: Resistor; Value: 10; Value_Code: 10R0; Tolerance_%: 5; Power_W: 0.75; Value2: 0.75W; VDC_V: 400; TempCo: 200 ppm/C; EIA_Code: E24; U/M: EA; AEC Category: Q200
R2 = CRCW0402100KFKED: RES, 100 k, 1%, 0.063 W, 0402; Manufacturer: Vishay-Dale; CompType: Resistor; Value: 100k; Res_ohm: 100000; Tolerance_%: 1; Power_W: 0.063; Value2: 0.063W; VDC_V: 50; TempCo: 100 ppm/C; SizeArea_mm2: 0.5; SizeZ_mm: 0.6; EIA_Code: E96; U/M: EA; AEC Category: Q200
R3 = RC1206FR-072M2L: RES, 2.2 M, 1%, 0.25 W, 1206; Manufacturer: Yageo America; CompType: Resistor; Value: 2.2Meg; Res_ohm: 2200000; Value_Code: 2M20; Tolerance_%: 1; Power_W: 0.25; Value2: 0.25W; VDC_V: 200; TempCo: 100 ppm/C; SizeArea_mm2: 5.12; SizeX_mm: 3.2; SizeY_mm: 1.6; SizeZ_mm: 1.35; U/M: EA; AEC Category: Q200
R4 = CRCW0402383KFKED: RES, 383 k, 1%, 0.063 W, 0402; Manufacturer: Vishay-Dale; CompType: Resistor; Value: 383k; Res_ohm: 383000; Tolerance_%: 1; Power_W: 0.063; Value2: 0.063W; VDC_V: 50; TempCo: 100 ppm/C; SizeArea_mm2: 0.5; SizeZ_mm: 0.6; EIA_Code: E96; U/M: EA; AEC Category: Q200
R5 = CRCW201033R0JNEF: RES, 33, 5%, 0.75 W, AEC-Q200 Grade 0, 2010; Manufacturer: Vishay-Dale; CompType: Resistor; Value: 33; Value_Code: 33R0; Tolerance_%: 5; Power_W: 0.75; Value2: 0.75W; VDC_V: 400; TempCo: 200 ppm/C; SizeArea_mm2: 12.5; SizeY_mm: 2.5; SizeZ_mm: 1.66; EIA_Code: E24; U/M: EA; AEC Category: Q200; AEC Qualified: Y; AEC Grade: 0
R6 = CRCW040251K1FKED: RES, 51.1 k, 1%, 0.063 W, 0402; Manufacturer: Vishay-Dale; CompType: Resistor; Value: 51.1k; Res_ohm: 51100; Value_Code: 51k1; Tolerance_%: 1; Power_W: 0.063; Value2: 0.063W; VDC_V: 50; TempCo: 100 ppm/C; SizeArea_mm2: 0.5; SizeZ_mm: 0.6; EIA_Code: E96; U/M: EA; AEC Category: Q200
R7 R9 = CRCW040210K0FKED: as R18 on sheet MSA004A_USSC
R8 = RC0603JR-0751KL: RES, 51 k, 5%, 0.1 W, 0603; Manufacturer: Yageo America; CompType: Resistor; Value: 51k; Res_ohm: 51000; Value_Code: 51k0; Tolerance_%: 5; Power_W: 0.1; Value2: 0.1W; VDC_V: 50; TempCo: 100 ppm/C; EIA_Code: E24; U/M: EA; AEC Category: Q200
R10 = RC0603JR-0710KL: RES, 10 k, 5%, 0.1 W, 0603; Manufacturer: Yageo America; CompType: Resistor; Value: 10k; Res_ohm: 10000; Value_Code: 10k0; Tolerance_%: 5; Power_W: 0.1; Value2: 0.1W; VDC_V: 50; TempCo: 100 ppm/C; EIA_Code: E24; U/M: EA; AEC Category: Q200; SizeArea_mm2: 1.28; SizeX_mm: 1.6; SizeY_mm: 0.8; SizeZ_mm: 1
U1 = TPS62175DQCR: 28V, 0.5A Step-Down Converter with Sleep Mode, DQC0010A; Alternate PartNumber: TPS62175DQCT; Manufacturer: Texas Instruments; SymbolCreator: a0411947; SizeArea_mm2: 6; SizeAreaWB_mm2: 12; SizeX_mm: 2; SizeY_mm: 3; SizeZ_mm: 0.8; CompType: IC; U/M: EA
U2 = LMR62421XMFX/NOPB: SIMPLE SWITCHER 24Vout, 2.1A Step-Up Voltage Regulator in SOT-23, DBV0005A; Alternate PartNumber: LMR62421XMFE/NOPB; Manufacturer: Texas Instruments; SymbolCreator: Altium; SizeArea_mm2: 8.12; SizeAreaWB_mm2: 14.82; SizeX_mm: 2.8; SizeY_mm: 2.9; SizeZ_mm: 1.45; CompType: IC; U/M: EA

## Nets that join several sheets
5VLP: MSA004A_USSC (J1/J3.21), MSA004A_PWR (D3.1 J7.3)
GND: MSA004A_USSC (21 pins), MSA004A_PWR (18 pins)
MAIN: MSA004A_USSC (D11.2 R24.2), MSA004A_PWR (6 pins)
VPWR: MSA004A_USSC (C8.1 J8.1 U3.15 U5.8), MSA004A_PWR (D2.1 R1.2 R8.1)
DS1_LED: MSA004A_USSC (J2/J4.38), MSA004A_PWR (D9.1)
F_DIAG_LED: MSA004A_USSC (J2/J4.39), MSA004A_PWR (D8.1)
IO: MSA004A_USSC (7 pins), MSA004A_PWR (J6.2)
V_DIAG_LED: MSA004A_USSC (J2/J4.40), MSA004A_PWR (D7.1)

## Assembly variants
001: not fitted C13 C14 C16 FID1 FID2 FID3 FID4 FID5 FID6 J6 J9 J10 J13 J14 R12 R12 R13 R17 R19 R30 R37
